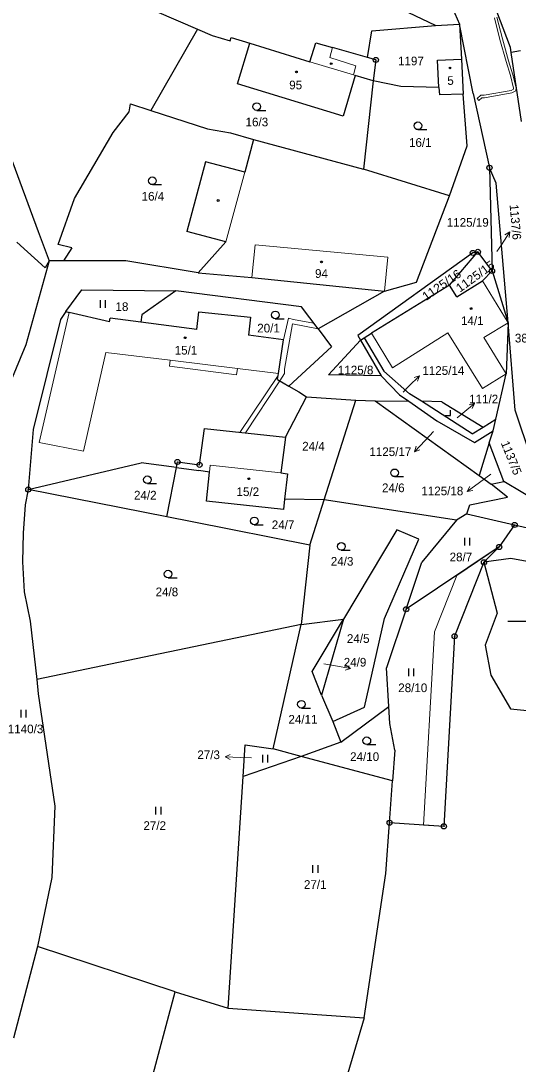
# Model space of a CAD drawing. Extents: x -765428 to -762163, y -1107632 to -1104975.
# Drawn here: x -764225.6 to -764128.3, y -1106238.6 to -1106034.3 of the extents above; entities that cross this region are included whole.
import ezdxf
from ezdxf.enums import TextEntityAlignment as Align

# ---------------------------------------------------------------- set-up
doc = ezdxf.new("R2010")
doc.units = 0
doc.header["$LTSCALE"] = 0.68
for name, color, linetype, lineweight in [('1', 7, 'Continuous', 25), ('13', 7, 'Continuous', 13), ('3', 7, 'Continuous', 25), ('4', 7, 'Continuous', 13), ('5', 7, 'Continuous', 25), ('7', 7, 'Continuous', 13), ('8', 7, 'Continuous', 25)]:
    doc.layers.add(name, color=color, linetype=linetype, lineweight=lineweight)
doc.layers.add('2', color=7, linetype='Continuous')

msp = doc.modelspace()

# ---------------------------------------------------------------- linework, layer by layer
at = {"layer": '1'}
for p, q in [((-764148.26, -1106015.89), (-764139.79, -1106034.92)), ((-764144.5, -1106035.19), (-764154.92, -1106030.18)), ((-764203.35, -1106030.65), (-764191.08, -1106035.94)), ((-764191.08, -1106035.94), (-764200.23, -1106051.84)), ((-764191.08, -1106035.94), (-764188.24, -1106037.16)), ((-764156.94, -1106036.25), (-764144.5, -1106035.19)), ((-764144.5, -1106035.19), (-764139.79, -1106034.92)), ((-764137.14, -1106048.54), (-764139.79, -1106034.92)), ((-764139.79, -1106034.92), (-764139.44, -1106041.78)), ((-764188.24, -1106037.16), (-764184.7, -1106038.24)), ((-764184.7, -1106038.24), (-764184.49, -1106037.58)), ((-764184.49, -1106037.58), (-764180.86, -1106038.69)), ((-764169.09, -1106042.3), (-764167.92, -1106038.6)), ((-764167.92, -1106038.6), (-764164.68, -1106039.54)), ((-764183.26, -1106046.64), (-764180.86, -1106038.69)), ((-764180.86, -1106038.69), (-764169.09, -1106042.3)), ((-764157.8, -1106041.49), (-764164.68, -1106039.54)), ((-764129.7, -1106040.51), (-764129.85, -1106039.54)), ((-764127.87, -1106040.16), (-764129.7, -1106040.51)), ((-764127.65, -1106053.99), (-764129.7, -1106040.51)), ((-764156.17, -1106041.95), (-764156.71, -1106046.06)), ((-764139.44, -1106041.78), (-764139.09, -1106048.62)), ((-764162.6, -1106052.95), (-764183.26, -1106046.64)), ((-764160.24, -1106044.99), (-764162.6, -1106052.95)), ((-764156.71, -1106046.06), (-764160.24, -1106044.99)), ((-764156.71, -1106046.06), (-764158.6, -1106063.34)), ((-764151.29, -1106047.12), (-764156.71, -1106046.06)), ((-764143.82, -1106047.32), (-764151.29, -1106047.12)), ((-764143.82, -1106047.32), (-764143.74, -1106048.81)), ((-764139.09, -1106048.62), (-764143.74, -1106048.81)), ((-764138.31, -1106058.79), (-764139.09, -1106048.62)), ((-764137.14, -1106048.54), (-764133.94, -1106063.05)), ((-764204.45, -1106052.11), (-764204.22, -1106050.55)), ((-764204.22, -1106050.55), (-764200.23, -1106051.84)), ((-764207.61, -1106056.16), (-764204.45, -1106052.11)), ((-764200.23, -1106051.84), (-764189.12, -1106055.44)), ((-764215.15, -1106069.08), (-764207.61, -1106056.16)), ((-764189.12, -1106055.44), (-764184.6, -1106056.21)), ((-764184.6, -1106056.21), (-764180.1, -1106057.54)), ((-764180.1, -1106057.54), (-764181.83, -1106063.95)), ((-764180.1, -1106057.54), (-764158.6, -1106063.34)), ((-764141.74, -1106068.54), (-764138.31, -1106058.79)), ((-764227.86, -1106060.33), (-764222.25, -1106075.51)), ((-764189.53, -1106061.87), (-764193.15, -1106075.51)), ((-764181.83, -1106063.95), (-764189.53, -1106061.87)), ((-764133.94, -1106063.05), (-764133.44, -1106083.26)), ((-764132.66, -1106066.08), (-764133.94, -1106063.05)), ((-764141.74, -1106068.54), (-764158.6, -1106063.34)), ((-764130.27, -1106093.42), (-764132.66, -1106066.08)), ((-764218.37, -1106078.06), (-764215.15, -1106069.08)), ((-764148.19, -1106085.46), (-764141.74, -1106068.54)), ((-764222.25, -1106075.51), (-764220.13, -1106081.27)), ((-764185.53, -1106077.59), (-764193.15, -1106075.51)), ((-764220.86, -1106082.63), (-764226.41, -1106077.61)), ((-764215.68, -1106078.71), (-764218.37, -1106078.06)), ((-764215.68, -1106078.71), (-764217.29, -1106081.27)), ((-764185.53, -1106077.59), (-764190.93, -1106083.65)), ((-764220.13, -1106081.27), (-764224.69, -1106097.76)), ((-764220.13, -1106081.27), (-764220.86, -1106082.63)), ((-764217.29, -1106081.27), (-764220.13, -1106081.27)), ((-764205.11, -1106081.27), (-764217.29, -1106081.27)), ((-764190.93, -1106083.65), (-764205.11, -1106081.27)), ((-764137.2, -1106079.73), (-764159.73, -1106095.9)), ((-764141.73, -1106086.03), (-764136.21, -1106079.53)), ((-764136.21, -1106079.53), (-764137.2, -1106079.73)), ((-764133.44, -1106083.26), (-764136.21, -1106079.53)), ((-764135.27, -1106085.23), (-764133.44, -1106083.26)), ((-764133.44, -1106083.26), (-764130.27, -1106093.42)), ((-764190.93, -1106083.65), (-764180.46, -1106084.52)), ((-764180.46, -1106084.52), (-764154.49, -1106087.24)), ((-764154.49, -1106087.24), (-764148.19, -1106085.46)), ((-764140.33, -1106088.32), (-764135.27, -1106085.23)), ((-764216.84, -1106091.22), (-764213.72, -1106086.93)), ((-764213.72, -1106086.93), (-764195.3, -1106087.17)), ((-764195.3, -1106087.17), (-764201.96, -1106091.84)), ((-764170.75, -1106090.26), (-764195.3, -1106087.17)), ((-764154.49, -1106087.24), (-764167.49, -1106094.62)), ((-764141.73, -1106086.03), (-764157.03, -1106095.46)), ((-764140.33, -1106088.32), (-764141.73, -1106086.03)), ((-764216.84, -1106091.22), (-764217.86, -1106092.77)), ((-764216.84, -1106091.22), (-764216.2, -1106091.37)), ((-764208.27, -1106093.2), (-764216.2, -1106091.37)), ((-764167.49, -1106094.62), (-764170.75, -1106090.26)), ((-764217.86, -1106092.77), (-764223.21, -1106114.33)), ((-764208.27, -1106093.2), (-764208.18, -1106092.53)), ((-764202.15, -1106093.32), (-764208.18, -1106092.53)), ((-764201.96, -1106091.84), (-764202.15, -1106093.32)), ((-764191.24, -1106094.75), (-764202.15, -1106093.32)), ((-764130.27, -1106093.42), (-764130.69, -1106103.41)), ((-764128.94, -1106110.55), (-764130.27, -1106093.42)), ((-764167.49, -1106094.62), (-764164.85, -1106098.09)), ((-764158.46, -1106096.33), (-764157.03, -1106095.46)), ((-764224.69, -1106097.76), (-764227.66, -1106104.99)), ((-764174.23, -1106096.75), (-764181.11, -1106095.83)), ((-764175.22, -1106103.31), (-764174.23, -1106096.75)), ((-764165.43, -1106103.63), (-764159.21, -1106096.79)), ((-764159.73, -1106095.9), (-764159.21, -1106096.79)), ((-764159.21, -1106096.79), (-764158.46, -1106096.33)), ((-764159.21, -1106096.79), (-764155.13, -1106103.79)), ((-764158.46, -1106096.33), (-764154.63, -1106102.91)), ((-764164.85, -1106098.09), (-764173.2, -1106105.8)), ((-764155.13, -1106103.79), (-764165.43, -1106103.63)), ((-764155.13, -1106103.79), (-764151.56, -1106107.52)), ((-764149.6, -1106107.29), (-764154.63, -1106102.91)), ((-764132.67, -1106112.27), (-764130.69, -1106103.41)), ((-764175.4, -1106104.5), (-764173.2, -1106105.8)), ((-764173.2, -1106105.8), (-764171.26, -1106106.95)), ((-764173.85, -1106115.82), (-764169.74, -1106107.91)), ((-764171.26, -1106106.95), (-764169.74, -1106107.91)), ((-764169.74, -1106107.91), (-764160.11, -1106108.53)), ((-764151.56, -1106107.52), (-764149.73, -1106108.78)), ((-764147.27, -1106108.77), (-764149.6, -1106107.29)), ((-764166.3, -1106128.06), (-764160.11, -1106108.53)), ((-764160.11, -1106108.53), (-764156.34, -1106108.67)), ((-764156.34, -1106108.67), (-764149.73, -1106108.78)), ((-764156.34, -1106108.67), (-764135.95, -1106123.28)), ((-764149.73, -1106108.78), (-764144.26, -1106112.63)), ((-764137.3, -1106115.13), (-764147.27, -1106108.77)), ((-764143.26, -1106108.87), (-764147.27, -1106108.77)), ((-764143.26, -1106108.87), (-764135.2, -1106113.83)), ((-764125.76, -1106119.84), (-764128.94, -1106110.55)), ((-764190.67, -1106121.22), (-764189.74, -1106114.14)), ((-764189.74, -1106114.14), (-764173.85, -1106115.82)), ((-764144.26, -1106112.63), (-764136.84, -1106116.85)), ((-764137.3, -1106115.13), (-764135.2, -1106113.83)), ((-764135.2, -1106113.83), (-764132.67, -1106112.27)), ((-764133.19, -1106114.59), (-764132.67, -1106112.27)), ((-764223.21, -1106114.33), (-764224.2, -1106126.06)), ((-764173.85, -1106115.82), (-764174.78, -1106122.82)), ((-764136.84, -1106116.85), (-764133.19, -1106114.59)), ((-764134, -1106116.89), (-764133.19, -1106114.59)), ((-764134, -1106116.89), (-764135.95, -1106123.28)), ((-764131.14, -1106124.47), (-764134, -1106116.89)), ((-764224.2, -1106126.06), (-764202.13, -1106120.81)), ((-764195.21, -1106121.73), (-764195, -1106120.66)), ((-764195.21, -1106121.73), (-764190.81, -1106122.32)), ((-764195, -1106120.66), (-764190.67, -1106121.22)), ((-764188.72, -1106122.63), (-764190.81, -1106122.32)), ((-764189.3, -1106128.34), (-764188.72, -1106122.63)), ((-764174.78, -1106122.82), (-764173.46, -1106122.97)), ((-764173.46, -1106122.97), (-764174.02, -1106127.97)), ((-764135.95, -1106123.28), (-764133.59, -1106125.04)), ((-764224.2, -1106126.06), (-764224.81, -1106129.03)), ((-764197.08, -1106131.43), (-764224.2, -1106126.06)), ((-764133.59, -1106125.04), (-764131.14, -1106124.47)), ((-764130.42, -1106127.58), (-764133.59, -1106125.04)), ((-764107.95, -1106138.44), (-764131.14, -1106124.47)), ((-764174.25, -1106129.99), (-764189.3, -1106128.34)), ((-764174.02, -1106127.97), (-764174.25, -1106129.99)), ((-764166.3, -1106128.06), (-764174.02, -1106127.97)), ((-764169.11, -1106136.95), (-764166.3, -1106128.06)), ((-764140.41, -1106132.06), (-764166.3, -1106128.06)), ((-764137.75, -1106129.07), (-764130.42, -1106127.58)), ((-764224.81, -1106129.03), (-764225.21, -1106134.62)), ((-764138.35, -1106130.81), (-764137.75, -1106129.07)), ((-764192.13, -1106132.41), (-764197.08, -1106131.43)), ((-764169.11, -1106136.95), (-764192.13, -1106132.41)), ((-764140.41, -1106132.06), (-764147.18, -1106140.31)), ((-764138.35, -1106130.81), (-764140.41, -1106132.06)), ((-764138.35, -1106130.81), (-764129.01, -1106132.99)), ((-764225.21, -1106134.62), (-764225.34, -1106140.22)), ((-764152.04, -1106133.92), (-764162.53, -1106151.43)), ((-764147.76, -1106135.78), (-764152.04, -1106133.92)), ((-764129.01, -1106132.99), (-764132.03, -1106137.31)), ((-764129.01, -1106132.99), (-764113.2, -1106136.69)), ((-764154.49, -1106151.34), (-764147.76, -1106135.78)), ((-764169.11, -1106136.95), (-764170.77, -1106152.47)), ((-764132.03, -1106137.31), (-764150.25, -1106149.51)), ((-764132.03, -1106137.31), (-764135.01, -1106140.3)), ((-764225.34, -1106140.22), (-764225, -1106146.09)), ((-764150.25, -1106149.51), (-764147.18, -1106140.31)), ((-764135.01, -1106140.3), (-764140.76, -1106154.78)), ((-764129.74, -1106139.56), (-764135.01, -1106140.3)), ((-764135.01, -1106140.3), (-764132.45, -1106150.27)), ((-764119.69, -1106141.37), (-764129.74, -1106139.56)), ((-764225, -1106146.09), (-764223.81, -1106151.85)), ((-764150.25, -1106149.51), (-764154.09, -1106161)), ((-764132.45, -1106150.27), (-764134.76, -1106156.54)), ((-764223.81, -1106151.85), (-764222.55, -1106163.24)), ((-764170.77, -1106152.47), (-764222.55, -1106163.24)), ((-764176.29, -1106176.84), (-764170.77, -1106152.47)), ((-764170.77, -1106152.47), (-764162.53, -1106151.43)), ((-764168.63, -1106161.7), (-764162.53, -1106151.43)), ((-764162.53, -1106151.43), (-764166.79, -1106166.35)), ((-764158.39, -1106168.65), (-764154.49, -1106151.34)), ((-764140.76, -1106154.78), (-764142.85, -1106192)), ((-764134.76, -1106156.54), (-764133.69, -1106162.39)), ((-764153.63, -1106168.54), (-764154.09, -1106161)), ((-764166.79, -1106166.35), (-764168.63, -1106161.7)), ((-764133.69, -1106162.39), (-764129.82, -1106168.98)), ((-764222.55, -1106163.24), (-764222.24, -1106166.03)), ((-764222.24, -1106166.03), (-764219.02, -1106188.03)), ((-764166.79, -1106166.35), (-764164.57, -1106171.5)), ((-764164.57, -1106171.5), (-764158.39, -1106168.65)), ((-764163.01, -1106175.53), (-764153.63, -1106168.54)), ((-764153.42, -1106171.84), (-764153.63, -1106168.54)), ((-764129.82, -1106168.98), (-764123.89, -1106169.55)), ((-764164.57, -1106171.5), (-764163.01, -1106175.53)), ((-764152.43, -1106177.11), (-764153.42, -1106171.84)), ((-764182.13, -1106182.26), (-764181.73, -1106176.03)), ((-764181.73, -1106176.03), (-764176.29, -1106176.84)), ((-764170.79, -1106178.31), (-764176.29, -1106176.84)), ((-764163.01, -1106175.53), (-764170.79, -1106178.31)), ((-764152.43, -1106177.11), (-764152.89, -1106183.11)), ((-764170.79, -1106178.31), (-764182.13, -1106182.26)), ((-764152.89, -1106183.11), (-764170.79, -1106178.31)), ((-764185.07, -1106227.57), (-764182.13, -1106182.26)), ((-764153.48, -1106191.3), (-764152.89, -1106183.11)), ((-764219.02, -1106188.03), (-764219.59, -1106201.99)), ((-764154.19, -1106201.21), (-764153.48, -1106191.3)), ((-764142.85, -1106192), (-764153.48, -1106191.3)), ((-764219.59, -1106201.99), (-764222.39, -1106215.5)), ((-764158.45, -1106229.51), (-764154.19, -1106201.21)), ((-764222.39, -1106215.5), (-764227.07, -1106233.48)), ((-764195.44, -1106224.39), (-764222.39, -1106215.5)), ((-764211.87, -1106285.29), (-764195.44, -1106224.39)), ((-764195.44, -1106224.39), (-764185.07, -1106227.57)), ((-764185.07, -1106227.57), (-764158.45, -1106229.51)), ((-764158.45, -1106229.51), (-764176.88, -1106291.46))]:
    msp.add_line(p, q, dxfattribs=at)
for points in [[(-764129.85, -1106039.54), (-764135.9, -1106023.45), (-764140, -1106014.74)], [(-764156.17, -1106041.95), (-764157.8, -1106041.49), (-764156.94, -1106036.25)], [(-764143.82, -1106047.32), (-764144.12, -1106041.97), (-764139.44, -1106041.78)], [(-764191.24, -1106094.75), (-764190.85, -1106091.24), (-764180.71, -1106092.34), (-764181.11, -1106095.83)], [(-764175.4, -1106104.5), (-764175.28, -1106103.74), (-764175.22, -1106103.31)], [(-764197.08, -1106131.43), (-764195.21, -1106121.73), (-764202.13, -1106120.81)]]:
    msp.add_lwpolyline(points, dxfattribs=at)
at = {"layer": '13'}
msp.add_lwpolyline([(-764132.98, -1106033.71), (-764131.89, -1106037.96), (-764130.7, -1106042.25), (-764129.84, -1106045.03), (-764129.22, -1106047.46), (-764129.26, -1106047.69), (-764129.7, -1106047.91), (-764135, -1106048.85), (-764135.63, -1106048.88), (-764136.33, -1106049.48), (-764136.01, -1106049.86), (-764135.43, -1106049.38), (-764134.94, -1106049.35), (-764129.54, -1106048.39), (-764128.8, -1106048.01), (-764128.72, -1106047.44), (-764129.36, -1106044.89), (-764130.22, -1106042.11), (-764131.41, -1106037.84), (-764132.5, -1106033.55)], dxfattribs=at)
for points in [[(-764182.81, -1106114.87), (-764181.69, -1106114.99), (-764174.97, -1106104.75), (-764174.06, -1106103.37), (-764174.03, -1106102.49), (-764172.49, -1106093.59), (-764167.49, -1106094.62), (-764168.36, -1106093.46), (-764172.28, -1106092.79), (-764173.24, -1106092.54), (-764173.44, -1106093.34), (-764174.23, -1106096.75), (-764175.22, -1106103.31), (-764175.28, -1106103.74)], [(-764146.84, -1106191.74), (-764142.85, -1106192), (-764140.76, -1106154.78), (-764135.01, -1106140.3), (-764132.03, -1106137.31), (-764140.33, -1106142.87), (-764144.72, -1106153.91)]]:
    msp.add_lwpolyline(points, close=True, dxfattribs=at)
at = {"layer": '3'}
for p, q in [((-764179.473, -1106051.83), (-764177.723, -1106051.83)), ((-764147.943, -1106055.6), (-764146.193, -1106055.6)), ((-764199.903, -1106066.37), (-764198.153, -1106066.37)), ((-764210.061, -1106090.48), (-764210.061, -1106088.98)), ((-764209.06, -1106090.48), (-764209.06, -1106088.98)), ((-764175.853, -1106092.62), (-764174.103, -1106092.62)), ((-764152.513, -1106123.54), (-764150.763, -1106123.54)), ((-764200.873, -1106124.89), (-764199.123, -1106124.89)), ((-764179.963, -1106132.95), (-764178.213, -1106132.95)), ((-764138.771, -1106137.01), (-764138.771, -1106135.51)), ((-764137.77, -1106137.01), (-764137.77, -1106135.51)), ((-764162.933, -1106137.94), (-764161.183, -1106137.94)), ((-764196.833, -1106143.37), (-764195.083, -1106143.37)), ((-764130.329, -1106151.83), (-764124.329, -1106151.83)), ((-764149.731, -1106162.57), (-764149.731, -1106161.07)), ((-764148.73, -1106162.57), (-764148.73, -1106161.07)), ((-764225.601, -1106170.66), (-764225.601, -1106169.16)), ((-764224.6, -1106170.66), (-764224.6, -1106169.16)), ((-764170.743, -1106168.85), (-764168.993, -1106168.85)), ((-764157.943, -1106175.99), (-764156.193, -1106175.99)), ((-764178.311, -1106179.52), (-764178.311, -1106178.02)), ((-764177.31, -1106179.52), (-764177.31, -1106178.02)), ((-764199.211, -1106189.71), (-764199.211, -1106188.21)), ((-764198.21, -1106189.71), (-764198.21, -1106188.21)), ((-764168.481, -1106201.12), (-764168.481, -1106199.62)), ((-764167.48, -1106201.12), (-764167.48, -1106199.62))]:
    msp.add_line(p, q, dxfattribs=at)
msp.add_lwpolyline([(-764142.581, -1106111.54), (-764141.58, -1106111.54), (-764141.58, -1106110.54)], dxfattribs=at)
for centre in [(-764179.4729, -1106051.0798), (-764147.9429, -1106054.8498), (-764199.9029, -1106065.6198), (-764175.8529, -1106091.8698), (-764152.5129, -1106122.7898), (-764200.8729, -1106124.1398), (-764179.9629, -1106132.1998), (-764162.9329, -1106137.1898), (-764196.8329, -1106142.6198), (-764170.7429, -1106168.0998), (-764157.9429, -1106175.2398)]:
    msp.add_circle(centre, 0.75, dxfattribs=at)
at = {"layer": '4'}
for p, q in [((-764164.68, -1106039.54), (-764165.21, -1106041.49)), ((-764165.21, -1106041.49), (-764160.06, -1106043.09)), ((-764160.06, -1106043.09), (-764160.56, -1106044.86)), ((-764181.83, -1106063.95), (-764185.53, -1106077.59)), ((-764180.46, -1106084.52), (-764179.81, -1106078.15)), ((-764179.81, -1106078.15), (-764153.86, -1106080.54)), ((-764153.86, -1106080.54), (-764154.49, -1106087.24)), ((-764130.27, -1106093.42), (-764135.27, -1106085.23)), ((-764216.2, -1106091.37), (-764222.08, -1106116.85)), ((-764135.06, -1106096.29), (-764130.27, -1106093.42)), ((-764157.03, -1106095.46), (-764152.94, -1106102.25)), ((-764152.94, -1106102.25), (-764142.08, -1106095.4)), ((-764142.08, -1106095.4), (-764135.33, -1106106.3)), ((-764130.69, -1106103.41), (-764135.06, -1106096.29)), ((-764209.01, -1106099.22), (-764213.4, -1106118.55)), ((-764196.43, -1106100.76), (-764209.01, -1106099.22)), ((-764183.27, -1106102.34), (-764196.43, -1106100.76)), ((-764175.22, -1106103.31), (-764183.27, -1106102.34)), ((-764135.33, -1106106.3), (-764130.69, -1106103.41)), ((-764222.08, -1106116.85), (-764213.4, -1106118.55)), ((-764188.72, -1106122.63), (-764188.59, -1106121.31)), ((-764188.59, -1106121.31), (-764174.78, -1106122.82))]:
    msp.add_line(p, q, dxfattribs=at)
for points in [[(-764169.09, -1106042.3), (-764160.56, -1106044.86), (-764160.24, -1106044.99)], [(-764196.43, -1106100.76), (-764196.54, -1106101.9), (-764183.46, -1106103.61), (-764183.27, -1106102.34)]]:
    msp.add_lwpolyline(points, dxfattribs=at)
at = {"layer": '5'}
for centre in [(-764164.8968, -1106042.6792), (-764171.7168, -1106044.2992), (-764141.6668, -1106043.5292), (-764187.0368, -1106069.4792), (-764166.8068, -1106081.4992), (-764137.5368, -1106090.6292), (-764193.4968, -1106096.3392), (-764181.0368, -1106123.9492)]:
    msp.add_circle(centre, 0.175, dxfattribs=at)
at = {"layer": '7'}
for p, q in [((-764129.932, -1106075.632), (-764130.907, -1106076.182)), ((-764147.638, -1106103.768), (-764148.7, -1106104.122)), ((-764136.851, -1106109.191), (-764137.94, -1106109.451)), ((-764148.597, -1106118.655), (-764147.547, -1106118.264)), ((-764138.277, -1106126.476), (-764137.176, -1106126.273)), ((-764161.135, -1106161.081), (-764162.034, -1106160.414)), ((-764185.689, -1106178.395), (-764184.706, -1106178.931))]:
    msp.add_line(p, q, dxfattribs=at)
for points in [[(-764132.51, -1106079.47), (-764131.61, -1106078.12), (-764129.932, -1106075.632), (-764130.077, -1106076.742)], [(-764150.86, -1106106.99), (-764149.76, -1106105.89), (-764147.638, -1106103.768), (-764147.992, -1106104.83)], [(-764140.23, -1106112.02), (-764139.15, -1106111.12), (-764136.851, -1106109.191), (-764137.296, -1106110.218)], [(-764144.9, -1106114.68), (-764146.55, -1106116.46), (-764148.597, -1106118.655), (-764148.28, -1106117.581)], [(-764133.67, -1106123.03), (-764135.88, -1106124.67), (-764138.277, -1106126.476), (-764137.778, -1106125.473)], [(-764166.33, -1106160.16), (-764164.09, -1106160.56), (-764161.135, -1106161.081), (-764162.208, -1106161.4)], [(-764180.49, -1106178.57), (-764182.69, -1106178.5), (-764185.689, -1106178.395), (-764184.671, -1106177.93)]]:
    msp.add_lwpolyline(points, dxfattribs=at)
at = {"layer": '8'}
for centre, radius in [((-764156.17, -1106041.9499), 0.5), ((-764156.17, -1106041.9499), 0.0303), ((-764133.94, -1106063.0499), 0.5), ((-764133.94, -1106063.0499), 0.0303), ((-764137.2, -1106079.7299), 0.5), ((-764136.21, -1106079.5299), 0.5), ((-764137.2, -1106079.7299), 0.0303), ((-764136.21, -1106079.5299), 0.0303), ((-764133.44, -1106083.2599), 0.5), ((-764133.44, -1106083.2599), 0.0303), ((-764195, -1106120.6599), 0.5), ((-764195, -1106120.6599), 0.0303), ((-764190.67, -1106121.2199), 0.5), ((-764190.67, -1106121.2199), 0.0303), ((-764224.2, -1106126.0599), 0.5), ((-764224.2, -1106126.0599), 0.0303), ((-764129.01, -1106132.9899), 0.5), ((-764129.01, -1106132.9899), 0.0303), ((-764132.03, -1106137.3099), 0.5), ((-764132.03, -1106137.3099), 0.0303), ((-764135.01, -1106140.2999), 0.5), ((-764135.01, -1106140.2999), 0.0303), ((-764150.25, -1106149.5099), 0.5), ((-764150.25, -1106149.5099), 0.0303), ((-764140.76, -1106154.7799), 0.5), ((-764140.76, -1106154.7799), 0.0303), ((-764153.48, -1106191.2999), 0.5), ((-764153.48, -1106191.2999), 0.0303), ((-764142.85, -1106191.9999), 0.5), ((-764142.85, -1106191.9999), 0.0303)]:
    msp.add_circle(centre, radius, dxfattribs=at)

# ---------------------------------------------------------------- texts
at = {"layer": '2'}
for s, p in [('1197', (-764149.31, -1106043.005)), ('5', (-764141.56, -1106046.835)), ('1125/19', (-764138.189, -1106074.605)), ('1125/8', (-764160.13, -1106103.515)), ('28/7', (-764139.529, -1106140.115)), ('24/3', (-764162.779, -1106140.965)), ('24/5', (-764159.629, -1106156.085)), ('28/10', (-764148.95, -1106165.725)), ('24/11', (-764170.44, -1106171.895)), ('24/10', (-764158.37, -1106179.205)), ('27/1', (-764168.039, -1106204.245))]:
    msp.add_text(s, height=1.7, dxfattribs=at).set_placement(p, align=Align.CENTER)
for s, p in [('95', (-764173.13, -1106047.705)), ('16/3', (-764181.67, -1106054.955)), ('16/1', (-764149.69, -1106058.965)), ('16/4', (-764202.02, -1106069.495)), ('94', (-764168.08, -1106084.625)), ('18', (-764207.13, -1106091.105)), ('20/1', (-764179.39, -1106095.305)), ('14/1', (-764139.51, -1106093.865)), ('15/1', (-764195.54, -1106099.635)), ('1125/14', (-764147.08, -1106103.615)), ('111/2', (-764137.92, -1106109.195)), ('24/4', (-764170.59, -1106118.425)), ('24/2', (-764203.51, -1106128.015)), ('15/2', (-764183.44, -1106127.335)), ('24/6', (-764154.97, -1106126.575)), ('24/7', (-764176.54, -1106133.815)), ('24/8', (-764199.28, -1106146.955)), ('24/9', (-764162.46, -1106160.725)), ('1140/3', (-764228.21, -1106173.785)), ('27/2', (-764201.66, -1106192.705))]:
    msp.add_text(s, height=1.7, dxfattribs=at).set_placement(p)
msp.add_text('1137/6', height=1.7, rotation=275, dxfattribs=at).set_placement((-764130.003, -1106070.297))
at = {"layer": '2', "width": 1.05}
for s, rotation, p in [('1125/15', 36, (-764139.72, -1106087.533)), ('1125/16', 35, (-764146.346, -1106089.178))]:
    msp.add_text(s, height=1.7, rotation=rotation, dxfattribs=at).set_placement(p)
at = {"layer": '2'}
for s, p in [('38/2', (-764124.539, -1106097.265)), ('1125/17', (-764149.23, -1106119.505)), ('1125/18', (-764139.06, -1106127.185)), ('27/3', (-764186.689, -1106178.835))]:
    msp.add_text(s, height=1.7, dxfattribs=at).set_placement(p, align=Align.RIGHT)
msp.add_text('1137/5', height=1.7, rotation=292, dxfattribs=at).set_placement((-764130.448, -1106120.1711), align=Align.CENTER)

doc.saveas('drawing.dxf')
